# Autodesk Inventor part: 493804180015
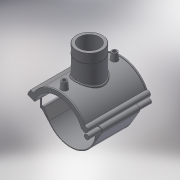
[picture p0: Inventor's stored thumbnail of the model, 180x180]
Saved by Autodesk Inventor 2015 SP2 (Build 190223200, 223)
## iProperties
Created: 2017-07
Part Number: 493804180015
Material: Generic
Description: PLASSON TRANSITION SADDLE 180-1.1/2"
Document SubType Name: Modeling
Designer: KIM
Density: 1 g/cm^3
Appearance: Default
Author: KIM
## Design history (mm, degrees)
derived "493804.ipt"
feature "Solid1::493804.ipt"
tag "TaggingFeature1"
body "Solid1"
other parameters: "B_" = 216, "H_" = 53, "L_" = 118, "d_t" = 6, "G_" = 44.845, "d148" = 2.7, "d160" = 2.7, "d169" = 2.1, "d192" = 4.2, "d1" = 207, "d2" = 216, "d3" = 45, "d4" = 118, "d5" = 0, "d6" = 0.1, "d8" = 0, "d19" = 6, "d20" = 6, "d21" = 70.8, "d23" = 0, "d24" = 35.4, "d26" = 0, "d27" = 3, "d28" = 3, "d29" = 3, "d31" = 6, "d32" = 0, "d33" = 0, "d34" = 0.6, "d40" = 107.64, "d41" = 62.783, "d43" = 0, "d45" = 0, "d47" = 156.5, "d48" = 58.2985, "d50" = 0, "d70" = 15, "d72" = 0, "d73" = 6, "d75" = 5, "d76" = 0, "d77" = 9, "d79" = 15, "d80" = 47.2, "d82" = 5 deg, "d84" = 4, "d85" = 14, "d86" = 0, "d87" = 3, "d88" = 0, "d89" = 1, "d90" = 1, "d91" = 94.4, "d92" = 0, "d93" = 0.5, "d94" = 94.73684, "d96" = 211.14, "d97" = 2.36, "d98" = 0, "d102" = 1.34535, "d103" = 44.845, "d104" = 31.8, "d105" = 0, "d106" = 35.876, "d108" = 0, "d109" = -17.66667, "d111" = 0.5, "d112" = 0.5, "d113" = 0, "d114" = 0.5, "d117" = 0.44845, "d120" = 140 deg, "d121" = 24.228, "d122" = 20 deg, "d123" = 414, "d124" = 124.2, "d126" = 0, "d143" = 185.4, "d145" = 20.76923, "d149" = 2.7, "d150" = 22.84615, "d153" = 118, "d154" = 0, "d156" = 103.5, "d157" = 160 deg, "d159" = 5.4, "d161" = 2.7, "d162" = 70.8, "d163" = 0, "d167" = 18, "d168" = 100.97561, "d170" = 2.1, "d172" = 0, "d173" = 1, "d176" = 20 deg, "d177" = 12.6, "d178" = 27, "d180" = 0, "d183" = 10.8, "d184" = 10.08, "d185" = 38.35, "d186" = 38.35, "d187" = 103.5, "d188" = 8.1, "d189" = 12.6, "d190" = 0, "d191" = 124.2, "d193" = 4.2, "d194" = 2.95, "d195" = 90 deg, "d197" = 0, "d199" = 0
